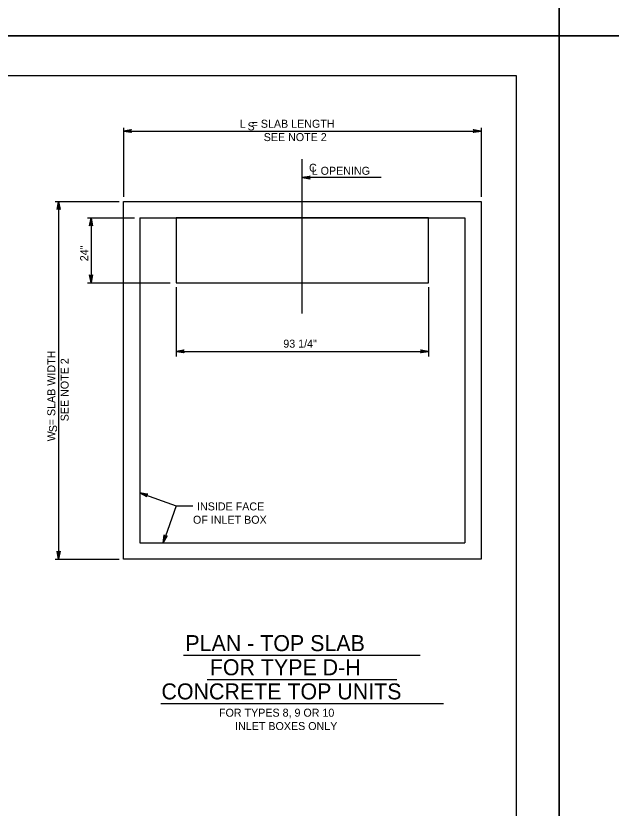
# Model space of a CAD drawing. Extents: x -6420 to 49575, y -4552 to 11624.
# Drawn here: x -1571 to -838, y 8725 to 9700 of the extents above; entities that cross this region are included whole.
import ezdxf

# ---------------------------------------------------------------- set-up
doc = ezdxf.new("R2010")
doc.units = 0
doc.layers.add('1', color=7, linetype='Continuous')
doc.layers.add('PLT-BNDY', color=7, linetype='Continuous')

msp = doc.modelspace()

# ---------------------------------------------------------------- linework, layer by layer
at = {"layer": '1'}
for p, q in [((-1438.11, 9562.04), (-1438.11, 9477.12)), ((-998.11, 9562.04), (-998.11, 9477.12)), ((-1438.11, 9558.06), (-998.11, 9558.06)), ((-1218.11, 9333.66), (-1218.11, 9523.45)), ((-1121.03, 9500.84), (-1218.11, 9500.84)), ((-1522.36, 9471.39), (-1443.38, 9471.39)), ((-1518.11, 9471.39), (-1518.11, 9031.39)), ((-1482.36, 9451.39), (-1424.48, 9451.39)), ((-1478.11, 9451.39), (-1478.11, 9371.39)), ((-1418.11, 9451.39), (-1018.11, 9451.39)), ((-1418.11, 9451.39), (-1418.11, 9051.39)), ((-1018.11, 9451.39), (-1018.11, 9051.39)), ((-1482.36, 9371.39), (-1380.92, 9371.39)), ((-1373.53, 9366.11), (-1373.53, 9280.85)), ((-1062.7, 9366.11), (-1062.7, 9280.85)), ((-1373.53, 9287.05), (-1062.7, 9287.05)), ((-1418.11, 9113.13), (-1373.4, 9097.24)), ((-1373.4, 9097.24), (-1389.56, 9051.39)), ((-1373.4, 9097.24), (-1352.96, 9097.24)), ((-1418.11, 9051.39), (-1018.11, 9051.39)), ((-1522.36, 9031.39), (-1443.38, 9031.39)), ((-1364.48, 8913.3), (-1073.16, 8913.3)), ((-1335.39, 8883.62), (-1101.82, 8883.62)), ((-1392.11, 8853.93), (-1044.43, 8853.93))]:
    msp.add_line(p, q, dxfattribs=at)
for points in [[(-954.49, 7775.47), (-954.49, 9625.87), (-3533.23, 9625.87), (-3533.23, 7775.47), (-954.49, 7775.47), (-954.49, 7861.95), (-1610.65, 7861.95), (-1610.65, 8074.15), (-954.49, 8074.15), (-954.49, 8169.17), (-1610.65, 8169.17), (-1610.65, 7775.47), (-1352.12, 7775.47), (-1352.12, 7861.95), (-1352.12, 7775.47), (-1099.49, 7775.47), (-1099.49, 7861.95), (-1099.49, 7821.54), (-954.49, 7821.54)], [(-1438.11, 9558.06), (-1428.33, 9559.89), (-1428.71, 9559.63), (-1429.08, 9559.37), (-1429.28, 9559.04), (-1429.47, 9558.71), (-1429.53, 9558.39), (-1429.58, 9558.06), (-1429.53, 9557.73), (-1429.47, 9557.4), (-1429.28, 9557.07), (-1429.08, 9556.74), (-1428.71, 9556.48), (-1428.33, 9556.22), (-1438.11, 9558.06), (-1428.71, 9556.48), (-1429.08, 9556.74), (-1438.11, 9558.06), (-1429.28, 9557.07), (-1429.47, 9557.4), (-1438.11, 9558.06), (-1429.53, 9557.73), (-1429.58, 9558.06), (-1438.11, 9558.06), (-1429.53, 9558.39), (-1429.47, 9558.71), (-1438.11, 9558.06), (-1429.28, 9559.04), (-1429.08, 9559.37), (-1438.11, 9558.06), (-1428.71, 9559.63)], [(-998.11, 9558.06), (-1007.9, 9556.22), (-1007.52, 9556.48), (-1007.15, 9556.74), (-1006.95, 9557.07), (-1006.76, 9557.4), (-1006.7, 9557.73), (-1006.64, 9558.06), (-1006.7, 9558.39), (-1006.76, 9558.71), (-1006.95, 9559.04), (-1007.15, 9559.37), (-1007.52, 9559.63), (-1007.9, 9559.89), (-998.11, 9558.06), (-1007.52, 9559.63), (-1007.15, 9559.37), (-998.11, 9558.06), (-1006.95, 9559.04), (-1006.76, 9558.71), (-998.11, 9558.06), (-1006.7, 9558.39), (-1006.64, 9558.06), (-998.11, 9558.06), (-1006.7, 9557.73), (-1006.76, 9557.4), (-998.11, 9558.06), (-1006.95, 9557.07), (-1007.15, 9556.74), (-998.11, 9558.06), (-1007.52, 9556.48)], [(-1218.11, 9500.84), (-1208.33, 9502.67), (-1208.71, 9502.41), (-1209.08, 9502.15), (-1209.28, 9501.82), (-1209.47, 9501.49), (-1209.53, 9501.17), (-1209.58, 9500.84), (-1209.53, 9500.51), (-1209.47, 9500.18), (-1209.28, 9499.85), (-1209.08, 9499.53), (-1208.71, 9499.26), (-1208.33, 9499), (-1218.11, 9500.84), (-1208.71, 9499.26), (-1209.08, 9499.53), (-1218.11, 9500.84), (-1209.28, 9499.85), (-1209.47, 9500.18), (-1218.11, 9500.84), (-1209.53, 9500.51), (-1209.58, 9500.84), (-1218.11, 9500.84), (-1209.53, 9501.17), (-1209.47, 9501.49), (-1218.11, 9500.84), (-1209.28, 9501.82), (-1209.08, 9502.15), (-1218.11, 9500.84), (-1208.71, 9502.41)], [(-1518.11, 9471.39), (-1516.28, 9461.6), (-1516.54, 9461.98), (-1516.8, 9462.36), (-1517.13, 9462.55), (-1517.46, 9462.75), (-1517.79, 9462.8), (-1518.11, 9462.86), (-1518.44, 9462.8), (-1518.77, 9462.75), (-1519.1, 9462.55), (-1519.43, 9462.36), (-1519.69, 9461.98), (-1519.95, 9461.6), (-1518.11, 9471.39), (-1519.69, 9461.98), (-1519.43, 9462.36), (-1518.11, 9471.39), (-1519.1, 9462.55), (-1518.77, 9462.75), (-1518.11, 9471.39), (-1518.44, 9462.8), (-1518.11, 9462.86), (-1518.11, 9471.39), (-1517.79, 9462.8), (-1517.46, 9462.75), (-1518.11, 9471.39), (-1517.13, 9462.55), (-1516.8, 9462.36), (-1518.11, 9471.39), (-1516.54, 9461.98)], [(-1478.11, 9451.39), (-1476.28, 9441.6), (-1476.54, 9441.98), (-1476.8, 9442.36), (-1477.13, 9442.55), (-1477.46, 9442.75), (-1477.79, 9442.8), (-1478.11, 9442.86), (-1478.44, 9442.8), (-1478.77, 9442.75), (-1479.1, 9442.55), (-1479.43, 9442.36), (-1479.69, 9441.98), (-1479.95, 9441.6), (-1478.11, 9451.39), (-1479.69, 9441.98), (-1479.43, 9442.36), (-1478.11, 9451.39), (-1479.1, 9442.55), (-1478.77, 9442.75), (-1478.11, 9451.39), (-1478.44, 9442.8), (-1478.11, 9442.86), (-1478.11, 9451.39), (-1477.79, 9442.8), (-1477.46, 9442.75), (-1478.11, 9451.39), (-1477.13, 9442.55), (-1476.8, 9442.36), (-1478.11, 9451.39), (-1476.54, 9441.98)], [(-1478.11, 9371.39), (-1479.95, 9381.17), (-1479.69, 9380.8), (-1479.43, 9380.42), (-1479.1, 9380.23), (-1478.77, 9380.03), (-1478.44, 9379.98), (-1478.11, 9379.92), (-1477.79, 9379.98), (-1477.46, 9380.03), (-1477.13, 9380.23), (-1476.8, 9380.42), (-1476.54, 9380.8), (-1476.28, 9381.17), (-1478.11, 9371.39), (-1476.54, 9380.8), (-1476.8, 9380.42), (-1478.11, 9371.39), (-1477.13, 9380.23), (-1477.46, 9380.03), (-1478.11, 9371.39), (-1477.79, 9379.98), (-1478.11, 9379.92), (-1478.11, 9371.39), (-1478.44, 9379.98), (-1478.77, 9380.03), (-1478.11, 9371.39), (-1479.1, 9380.23), (-1479.43, 9380.42), (-1478.11, 9371.39), (-1479.69, 9380.8)], [(-1373.53, 9287.05), (-1363.75, 9288.88), (-1364.12, 9288.62), (-1364.5, 9288.36), (-1364.69, 9288.03), (-1364.89, 9287.7), (-1364.94, 9287.38), (-1365, 9287.05), (-1364.94, 9286.72), (-1364.89, 9286.39), (-1364.69, 9286.06), (-1364.5, 9285.74), (-1364.12, 9285.47), (-1363.75, 9285.21), (-1373.53, 9287.05), (-1364.12, 9285.47), (-1364.5, 9285.74), (-1373.53, 9287.05), (-1364.69, 9286.06), (-1364.89, 9286.39), (-1373.53, 9287.05), (-1364.94, 9286.72), (-1365, 9287.05), (-1373.53, 9287.05), (-1364.94, 9287.38), (-1364.89, 9287.7), (-1373.53, 9287.05), (-1364.69, 9288.03), (-1364.5, 9288.36), (-1373.53, 9287.05), (-1364.12, 9288.62)], [(-1062.7, 9287.05), (-1072.48, 9285.21), (-1072.11, 9285.47), (-1071.73, 9285.74), (-1071.54, 9286.06), (-1071.34, 9286.39), (-1071.29, 9286.72), (-1071.23, 9287.05), (-1071.29, 9287.38), (-1071.34, 9287.7), (-1071.54, 9288.03), (-1071.73, 9288.36), (-1072.11, 9288.62), (-1072.48, 9288.88), (-1062.7, 9287.05), (-1072.11, 9288.62), (-1071.73, 9288.36), (-1062.7, 9287.05), (-1071.54, 9288.03), (-1071.34, 9287.7), (-1062.7, 9287.05), (-1071.29, 9287.38), (-1071.23, 9287.05), (-1062.7, 9287.05), (-1071.29, 9286.72), (-1071.34, 9286.39), (-1062.7, 9287.05), (-1071.54, 9286.06), (-1071.73, 9285.74), (-1062.7, 9287.05), (-1072.11, 9285.47)], [(-1418.11, 9113.13), (-1408.28, 9111.59), (-1408.72, 9111.47), (-1409.16, 9111.35), (-1409.46, 9111.1), (-1409.75, 9110.86), (-1409.91, 9110.57), (-1410.08, 9110.28), (-1410.13, 9109.95), (-1410.19, 9109.62), (-1410.12, 9109.25), (-1410.04, 9108.87), (-1409.78, 9108.5), (-1409.51, 9108.13), (-1418.11, 9113.13), (-1409.78, 9108.5), (-1410.04, 9108.87), (-1418.11, 9113.13), (-1410.12, 9109.25), (-1410.19, 9109.62), (-1418.11, 9113.13), (-1410.13, 9109.95), (-1410.08, 9110.28), (-1418.11, 9113.13), (-1409.91, 9110.57), (-1409.75, 9110.86), (-1418.11, 9113.13), (-1409.46, 9111.1), (-1409.16, 9111.35), (-1418.11, 9113.13), (-1408.72, 9111.47)], [(-1389.56, 9051.39), (-1388.04, 9061.23), (-1387.92, 9060.79), (-1387.8, 9060.34), (-1387.55, 9060.05), (-1387.31, 9059.76), (-1387.02, 9059.6), (-1386.73, 9059.43), (-1386.4, 9059.38), (-1386.07, 9059.32), (-1385.7, 9059.4), (-1385.32, 9059.47), (-1384.95, 9059.74), (-1384.58, 9060.01), (-1389.56, 9051.39), (-1384.95, 9059.74), (-1385.32, 9059.47), (-1389.56, 9051.39), (-1385.7, 9059.4), (-1386.07, 9059.32), (-1389.56, 9051.39), (-1386.4, 9059.38), (-1386.73, 9059.43), (-1389.56, 9051.39), (-1387.02, 9059.6), (-1387.31, 9059.76), (-1389.56, 9051.39), (-1387.55, 9060.05), (-1387.8, 9060.34), (-1389.56, 9051.39), (-1387.92, 9060.79)], [(-1518.11, 9031.39), (-1519.95, 9041.17), (-1519.69, 9040.8), (-1519.43, 9040.42), (-1519.1, 9040.23), (-1518.77, 9040.03), (-1518.44, 9039.98), (-1518.11, 9039.92), (-1517.79, 9039.98), (-1517.46, 9040.03), (-1517.13, 9040.23), (-1516.8, 9040.42), (-1516.54, 9040.8), (-1516.28, 9041.17), (-1518.11, 9031.39), (-1516.54, 9040.8), (-1516.8, 9040.42), (-1518.11, 9031.39), (-1517.13, 9040.23), (-1517.46, 9040.03), (-1518.11, 9031.39), (-1517.79, 9039.98), (-1518.11, 9039.92), (-1518.11, 9031.39), (-1518.44, 9039.98), (-1518.77, 9040.03), (-1518.11, 9031.39), (-1519.1, 9040.23), (-1519.43, 9040.42), (-1518.11, 9031.39), (-1519.69, 9040.8)]]:
    msp.add_lwpolyline(points, dxfattribs=at)
for points in [[(-1438.11, 9471.39), (-998.11, 9471.39), (-998.11, 9031.39), (-1438.11, 9031.39)], [(-1373.53, 9371.39), (-1062.7, 9371.39), (-1062.7, 9451.39), (-1373.53, 9451.39)]]:
    msp.add_lwpolyline(points, close=True, dxfattribs=at)
at = {"layer": 'PLT-BNDY'}
for points in [[(-3661.18, 11623.9), (-901.99, 11623.9), (-901.99, 9675.08), (-3661.18, 9675.08)], [(-901.99, 11623.9), (1857.19, 11623.9), (1857.19, 9675.08), (-901.99, 9675.08)], [(-3661.18, 9675.08), (-901.99, 9675.08), (-901.99, 7726.26), (-3661.18, 7726.26)], [(-901.99, 9675.08), (1857.19, 9675.08), (1857.19, 7726.26), (-901.99, 7726.26)]]:
    msp.add_lwpolyline(points, close=True, dxfattribs=at)

# ---------------------------------------------------------------- texts
at = {"layer": '1'}
for s, height, p in [('L  = SLAB LENGTH', 9.8425, (-1295.14, 9562.05)), ('S', 9.84, (-1285.48, 9558.9)), ('SEE NOTE 2', 9.843, (-1265.62, 9545.65)), ('C', 9.84, (-1209.85, 9507.93)), ('L OPENING', 9.843, (-1206.52, 9504.22)), ('93 1/4"', 9.843, (-1241.52, 9291.59)), ('INSIDE FACE', 9.8425, (-1347.67, 9091.45)), ('OF INLET BOX', 9.8425, (-1352.67, 9075.05)), ('PLAN - TOP SLAB', 19.685, (-1362.03, 8918.39)), ('FOR TYPE D-H', 19.685, (-1331.96, 8888.7)), ('CONCRETE TOP UNITS', 19.685, (-1391.48, 8859.02)), ('FOR TYPES 8, 9 OR 10', 9.8425, (-1320.63, 8837.73)), ('INLET BOXES ONLY', 9.8425, (-1300.83, 8821.33))]:
    msp.add_text(s, height=height, dxfattribs=at).set_placement(p)
for s, height, p in [('24"', 9.843, (-1481.65, 9397.91)), ('W  = SLAB WIDTH', 9.8425, (-1522.12, 9176.42)), ('SEE NOTE 2', 9.843, (-1505.71, 9201.02)), ('S', 9.84, (-1519.96, 9187.68))]:
    msp.add_text(s, height=height, rotation=90, dxfattribs=at).set_placement(p)

doc.saveas('drawing.dxf')
